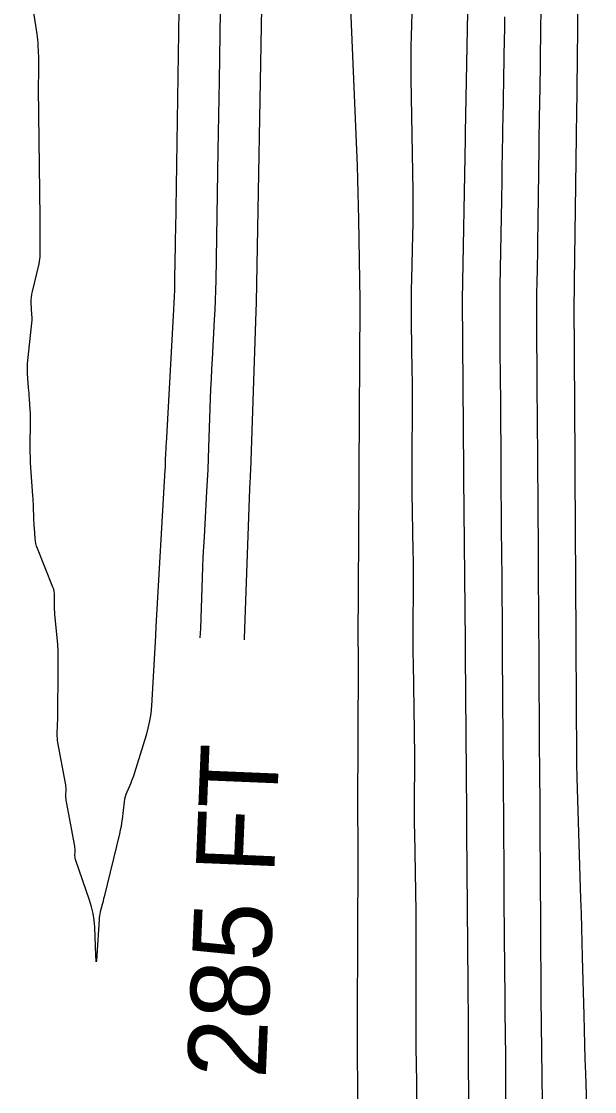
# Model space of a CAD drawing. Extents: x 1768942 to 1774819, y 723037 to 732099.
# Drawn here: x 1770471.7 to 1770515.4, y 730556.6 to 730638.3 of the extents above; entities that cross this region are included whole.
import ezdxf

# ---------------------------------------------------------------- set-up
doc = ezdxf.new("R2010")
doc.units = 0
doc.layers.add('R_Contour Annot', color=7, linetype='Continuous')
doc.layers.add('R_Contours', color=7, linetype='Continuous')

msp = doc.modelspace()

# ---------------------------------------------------------------- linework, layer by layer
at = {"layer": 'R_Contours'}
for points in [[(1770501.917, 730552.791), (1770501.837, 730559.061), (1770501.831, 730559.609), (1770501.826, 730560.157), (1770501.822, 730560.705), (1770501.821, 730561.253), (1770501.817, 730563.445), (1770501.816, 730563.993), (1770501.816, 730564.541), (1770501.817, 730565.089), (1770501.819, 730565.637), (1770501.829, 730568.039), (1770501.829, 730568.622), (1770501.827, 730569.205), (1770501.822, 730569.788), (1770501.813, 730570.371), (1770501.711, 730576.362), (1770501.702, 730577.008), (1770501.696, 730577.654), (1770501.694, 730578.3), (1770501.695, 730578.946), (1770501.708, 730581.529), (1770501.709, 730582.175), (1770501.707, 730582.821), (1770501.702, 730583.467), (1770501.693, 730584.113), (1770501.608, 730589.342), (1770501.598, 730590.051), (1770501.593, 730590.76), (1770501.591, 730591.469), (1770501.593, 730592.178), (1770501.609, 730595.014), (1770501.611, 730595.723), (1770501.61, 730596.432), (1770501.604, 730597.141), (1770501.595, 730597.85), (1770501.526, 730602.313), (1770501.517, 730603.086), (1770501.511, 730603.858), (1770501.51, 730604.631), (1770501.513, 730605.403), (1770501.533, 730608.493), (1770501.536, 730609.265), (1770501.535, 730610.038), (1770501.53, 730610.81), (1770501.52, 730611.583), (1770501.466, 730615.278), (1770501.458, 730616.114), (1770501.458, 730616.949), (1770501.467, 730617.784), (1770501.485, 730618.62), (1770501.571, 730621.96), (1770501.588, 730622.796), (1770501.596, 730623.631), (1770501.596, 730624.466), (1770501.587, 730625.302), (1770501.448, 730633.907), (1770501.439, 730634.721), (1770501.44, 730635.536), (1770501.45, 730636.35), (1770501.469, 730637.164), (1770501.767, 730647.369)], [(1770483.735, 730640.793), (1770483.437, 730622.303), (1770483.428, 730621.801), (1770483.42, 730621.299), (1770483.412, 730620.797), (1770483.403, 730620.295), (1770483.368, 730618.288), (1770483.357, 730617.786), (1770483.341, 730617.284), (1770483.32, 730616.783), (1770483.294, 730616.281), (1770482.721, 730606.065), (1770482.712, 730605.898), (1770482.704, 730605.73), (1770482.697, 730605.563), (1770482.691, 730605.396), (1770482.668, 730604.726), (1770482.662, 730604.559), (1770482.655, 730604.392), (1770482.646, 730604.225), (1770482.637, 730604.058), (1770481.948, 730592.095), (1770481.945, 730592.036), (1770481.942, 730591.978), (1770481.939, 730591.919), (1770481.937, 730591.86), (1770481.929, 730591.626), (1770481.927, 730591.567), (1770481.924, 730591.509), (1770481.921, 730591.45), (1770481.918, 730591.391), (1770481.601, 730586.045), (1770481.55, 730585.475), (1770481.465, 730584.91), (1770481.346, 730584.352), (1770481.194, 730583.8), (1770480.287, 730580.868), (1770480.229, 730580.688), (1770480.166, 730580.51), (1770480.098, 730580.333), (1770480.026, 730580.158), (1770479.728, 730579.462), (1770479.659, 730579.286), (1770479.604, 730579.107), (1770479.562, 730578.924), (1770479.533, 730578.738), (1770479.371, 730577.404), (1770479.332, 730577.12), (1770479.285, 730576.837), (1770479.23, 730576.556), (1770479.166, 730576.276), (1770477.995, 730571.473), (1770477.959, 730571.329), (1770477.923, 730571.185), (1770477.886, 730571.042), (1770477.849, 730570.899), (1770477.698, 730570.326), (1770477.664, 730570.182), (1770477.638, 730570.037), (1770477.618, 730569.891), (1770477.606, 730569.744), (1770477.452, 730567.012), (1770477.425, 730566.634), (1770477.4, 730566.508), (1770477.378, 730566.634), (1770477.358, 730567.013), (1770477.277, 730569.17), (1770477.238, 730569.694), (1770477.161, 730570.211), (1770477.044, 730570.72), (1770476.888, 730571.222), (1770475.828, 730574.242), (1770475.802, 730574.33), (1770475.784, 730574.419), (1770475.773, 730574.509), (1770475.771, 730574.6), (1770475.779, 730574.969), (1770475.779, 730575.061), (1770475.773, 730575.152), (1770475.764, 730575.244), (1770475.749, 730575.335), (1770475.122, 730578.728), (1770475.104, 730578.844), (1770475.091, 730578.962), (1770475.084, 730579.079), (1770475.083, 730579.197), (1770475.091, 730579.671), (1770475.09, 730579.789), (1770475.083, 730579.907), (1770475.07, 730580.024), (1770475.051, 730580.14), (1770474.471, 730583.253), (1770474.445, 730583.417), (1770474.428, 730583.582), (1770474.42, 730583.748), (1770474.421, 730583.914), (1770474.442, 730584.581), (1770474.447, 730584.747), (1770474.451, 730584.914), (1770474.454, 730585.081), (1770474.456, 730585.247), (1770474.495, 730588.843), (1770474.497, 730588.999), (1770474.497, 730589.156), (1770474.497, 730589.313), (1770474.495, 730589.469), (1770474.488, 730590.096), (1770474.485, 730590.252), (1770474.478, 730590.409), (1770474.469, 730590.565), (1770474.456, 730590.721), (1770474.242, 730593.041), (1770474.228, 730593.215), (1770474.218, 730593.389), (1770474.213, 730593.563), (1770474.212, 730593.738), (1770474.216, 730594.436), (1770474.209, 730594.609), (1770474.185, 730594.779), (1770474.145, 730594.946), (1770474.088, 730595.109), (1770472.904, 730598.05), (1770472.838, 730598.234), (1770472.787, 730598.423), (1770472.75, 730598.614), (1770472.729, 730598.809), (1770472.675, 730599.596), (1770472.662, 730599.792), (1770472.651, 730599.989), (1770472.642, 730600.186), (1770472.635, 730600.383), (1770472.607, 730601.243), (1770472.599, 730601.451), (1770472.589, 730601.66), (1770472.577, 730601.869), (1770472.563, 730602.077), (1770472.406, 730604.227), (1770472.382, 730604.623), (1770472.365, 730605.019), (1770472.357, 730605.415), (1770472.357, 730605.812), (1770472.376, 730607.768), (1770472.376, 730607.981), (1770472.372, 730608.193), (1770472.363, 730608.406), (1770472.35, 730608.618), (1770472.291, 730609.467), (1770472.276, 730609.679), (1770472.261, 730609.892), (1770472.246, 730610.104), (1770472.232, 730610.316), (1770472.156, 730611.398), (1770472.145, 730611.648), (1770472.144, 730611.899), (1770472.154, 730612.149), (1770472.176, 730612.4), (1770472.464, 730615.022), (1770472.484, 730615.243), (1770472.494, 730615.464), (1770472.495, 730615.685), (1770472.487, 730615.907), (1770472.437, 730616.794), (1770472.432, 730617.015), (1770472.444, 730617.234), (1770472.472, 730617.452), (1770472.516, 730617.669), (1770473.029, 730619.777), (1770473.067, 730619.955), (1770473.095, 730620.134), (1770473.111, 730620.314), (1770473.118, 730620.496), (1770473.122, 730621.245), (1770473.123, 730621.417), (1770473.123, 730621.589), (1770473.121, 730621.762), (1770473.119, 730621.934), (1770473.11, 730622.623), (1770473.107, 730622.795), (1770473.105, 730622.967), (1770473.103, 730623.14), (1770473.101, 730623.312), (1770472.997, 730633.147), (1770472.996, 730633.345), (1770472.996, 730633.543), (1770472.997, 730633.741), (1770473, 730633.938), (1770473.014, 730634.729), (1770473.016, 730634.927), (1770473.015, 730635.125), (1770473.012, 730635.322), (1770473.005, 730635.52), (1770472.969, 730636.432), (1770472.957, 730636.65), (1770472.939, 730636.867), (1770472.915, 730637.083), (1770472.884, 730637.299), (1770471.679, 730645.03)], [(1770514.198, 730642.238), (1770514.055, 730630.913), (1770514.053, 730630.796), (1770514.051, 730630.68), (1770514.05, 730630.563), (1770514.047, 730630.447), (1770514.039, 730629.98), (1770514.036, 730629.864), (1770514.034, 730629.747), (1770514.033, 730629.631), (1770514.031, 730629.514), (1770513.89, 730618.391), (1770513.888, 730618.258), (1770513.886, 730618.124), (1770513.884, 730617.991), (1770513.882, 730617.857), (1770513.871, 730617.324), (1770513.869, 730617.19), (1770513.868, 730617.057), (1770513.867, 730616.923), (1770513.868, 730616.79), (1770513.934, 730604.906), (1770513.935, 730604.813), (1770513.935, 730604.721), (1770513.936, 730604.628), (1770513.937, 730604.535), (1770513.94, 730604.164), (1770513.941, 730604.071), (1770513.941, 730603.978), (1770513.942, 730603.885), (1770513.942, 730603.792), (1770514.011, 730591.301), (1770514.011, 730591.261), (1770514.011, 730591.222), (1770514.012, 730591.182), (1770514.012, 730591.142), (1770514.013, 730590.983), (1770514.014, 730590.943), (1770514.014, 730590.903), (1770514.014, 730590.864), (1770514.014, 730590.824), (1770514.062, 730581.98), (1770514.065, 730581.623), (1770514.07, 730581.266), (1770514.078, 730580.909), (1770514.088, 730580.551), (1770514.376, 730571.325), (1770514.41, 730570.214), (1770514.442, 730569.104), (1770514.473, 730567.994), (1770514.502, 730566.884), (1770514.615, 730562.442), (1770514.645, 730561.332), (1770514.676, 730560.221), (1770514.71, 730559.111), (1770514.745, 730558.001), (1770515.444, 730536.883)], [(1770505.845, 730552.106), (1770505.806, 730562.913), (1770505.805, 730563.072), (1770505.804, 730563.231), (1770505.803, 730563.39), (1770505.802, 730563.548), (1770505.795, 730564.183), (1770505.793, 730564.342), (1770505.792, 730564.501), (1770505.79, 730564.66), (1770505.789, 730564.818), (1770505.692, 730576.426), (1770505.691, 730576.547), (1770505.69, 730576.667), (1770505.69, 730576.788), (1770505.689, 730576.908), (1770505.686, 730577.391), (1770505.686, 730577.512), (1770505.685, 730577.632), (1770505.684, 730577.753), (1770505.683, 730577.874), (1770505.581, 730589.955), (1770505.581, 730590.036), (1770505.58, 730590.117), (1770505.58, 730590.198), (1770505.579, 730590.28), (1770505.577, 730590.604), (1770505.577, 730590.686), (1770505.576, 730590.767), (1770505.576, 730590.848), (1770505.575, 730590.929), (1770505.469, 730603.479), (1770505.468, 730603.522), (1770505.468, 730603.564), (1770505.468, 730603.607), (1770505.467, 730603.649), (1770505.466, 730603.82), (1770505.466, 730603.862), (1770505.466, 730603.905), (1770505.466, 730603.947), (1770505.465, 730603.99), (1770505.354, 730617), (1770505.354, 730617.041), (1770505.354, 730617.055), (1770505.589, 730629.312), (1770505.59, 730629.352), (1770505.591, 730629.393), (1770505.591, 730629.433), (1770505.592, 730629.474), (1770505.594, 730629.635), (1770505.594, 730629.675), (1770505.595, 730629.716), (1770505.596, 730629.756), (1770505.596, 730629.797), (1770505.822, 730641.632)], [(1770511.457, 730555.794), (1770511.374, 730563.757), (1770511.37, 730564.218), (1770511.365, 730564.679), (1770511.361, 730565.139), (1770511.357, 730565.6), (1770511.342, 730567.443), (1770511.338, 730567.903), (1770511.335, 730568.364), (1770511.332, 730568.824), (1770511.329, 730569.285), (1770511.29, 730576.745), (1770511.287, 730577.256), (1770511.283, 730577.766), (1770511.28, 730578.277), (1770511.276, 730578.788), (1770511.258, 730580.83), (1770511.254, 730581.341), (1770511.251, 730581.852), (1770511.247, 730582.362), (1770511.244, 730582.873), (1770511.207, 730589.738), (1770511.204, 730590.298), (1770511.201, 730590.858), (1770511.196, 730591.418), (1770511.192, 730591.977), (1770511.173, 730594.216), (1770511.168, 730594.776), (1770511.164, 730595.336), (1770511.161, 730595.896), (1770511.157, 730596.455), (1770511.123, 730602.738), (1770511.119, 730603.346), (1770511.115, 730603.954), (1770511.111, 730604.561), (1770511.106, 730605.169), (1770511.085, 730607.601), (1770511.08, 730608.209), (1770511.076, 730608.817), (1770511.071, 730609.425), (1770511.068, 730610.032), (1770511.035, 730615.846), (1770511.034, 730616.449), (1770511.036, 730617.053), (1770511.042, 730617.656), (1770511.052, 730618.26), (1770511.098, 730620.674), (1770511.109, 730621.277), (1770511.119, 730621.881), (1770511.129, 730622.484), (1770511.137, 730623.088), (1770511.206, 730628.576), (1770511.214, 730629.156), (1770511.223, 730629.737), (1770511.233, 730630.317), (1770511.243, 730630.898), (1770511.287, 730633.22), (1770511.298, 730633.8), (1770511.308, 730634.381), (1770511.316, 730634.961), (1770511.324, 730635.542), (1770511.397, 730641.305)], [(1770488.719, 730591.084), (1770488.724, 730591.201), (1770489.119, 730602.571), (1770489.123, 730602.691), (1770489.128, 730602.811), (1770489.134, 730602.931), (1770489.141, 730603.051), (1770489.168, 730603.531), (1770489.175, 730603.651), (1770489.181, 730603.771), (1770489.186, 730603.891), (1770489.19, 730604.011), (1770489.601, 730616.135), (1770489.603, 730616.194), (1770489.606, 730616.252), (1770489.609, 730616.31), (1770489.612, 730616.368), (1770489.625, 730616.601), (1770489.628, 730616.659), (1770489.63, 730616.718), (1770489.632, 730616.776), (1770489.633, 730616.834), (1770490.05, 730640.716)], [(1770496.753, 730640.476), (1770497.305, 730627.247), (1770497.344, 730626.221), (1770497.377, 730625.194), (1770497.404, 730624.167), (1770497.423, 730623.14), (1770497.522, 730617.007), (1770497.523, 730616.992), (1770497.523, 730616.976), (1770497.522, 730616.961), (1770497.522, 730616.945), (1770497.521, 730616.883), (1770497.52, 730616.867), (1770497.52, 730616.852), (1770497.52, 730616.836), (1770497.52, 730616.82), (1770497.521, 730616.755), (1770497.521, 730616.739), (1770497.521, 730616.723), (1770497.521, 730616.707), (1770497.521, 730616.69), (1770497.438, 730603.975), (1770497.438, 730603.892), (1770497.438, 730603.809), (1770497.438, 730603.727), (1770497.439, 730603.644), (1770497.445, 730603.313), (1770497.446, 730603.231), (1770497.446, 730603.148), (1770497.446, 730603.065), (1770497.446, 730602.983), (1770497.378, 730591.057), (1770497.378, 730590.908), (1770497.378, 730590.759), (1770497.379, 730590.611), (1770497.381, 730590.462), (1770497.391, 730589.866), (1770497.393, 730589.717), (1770497.394, 730589.568), (1770497.395, 730589.42), (1770497.394, 730589.271), (1770497.341, 730578.131), (1770497.34, 730577.917), (1770497.341, 730577.702), (1770497.343, 730577.487), (1770497.346, 730577.272), (1770497.36, 730576.413), (1770497.364, 730576.199), (1770497.365, 730575.984), (1770497.366, 730575.769), (1770497.366, 730575.554), (1770497.333, 730567.303), (1770497.329, 730565.97), (1770497.326, 730564.637), (1770497.326, 730563.304), (1770497.327, 730561.971), (1770497.341, 730554.495)], [(1770486.865, 730639.05), (1770486.78, 730633.737), (1770486.758, 730632.408), (1770486.736, 730631.08), (1770486.713, 730629.751), (1770486.69, 730628.423), (1770486.517, 730618.505), (1770486.5, 730617.753), (1770486.476, 730617.001), (1770486.445, 730616.25), (1770486.407, 730615.498), (1770486.238, 730612.493), (1770486.198, 730611.742), (1770486.162, 730610.991), (1770486.13, 730610.239), (1770486.103, 730609.487), (1770485.976, 730605.755), (1770485.945, 730604.918), (1770485.909, 730604.082), (1770485.869, 730603.245), (1770485.823, 730602.41), (1770485.624, 730598.949), (1770485.581, 730598.172), (1770485.543, 730597.394), (1770485.509, 730596.616), (1770485.48, 730595.838), (1770485.372, 730592.725), (1770485.342, 730591.947), (1770485.311, 730591.226)], [(1770508.573, 730638.622), (1770508.565, 730638.082), (1770508.556, 730637.541), (1770508.547, 730637.001), (1770508.427, 730630.749), (1770508.418, 730630.237), (1770508.41, 730629.726), (1770508.402, 730629.215), (1770508.395, 730628.704), (1770508.369, 730626.659), (1770508.362, 730626.148), (1770508.354, 730625.637), (1770508.346, 730625.126), (1770508.336, 730624.614), (1770508.211, 730618.083), (1770508.203, 730617.566), (1770508.198, 730617.049), (1770508.196, 730616.532), (1770508.197, 730616.015), (1770508.208, 730613.947), (1770508.212, 730613.43), (1770508.215, 730612.913), (1770508.219, 730612.396), (1770508.223, 730611.879), (1770508.282, 730605.049), (1770508.286, 730604.489), (1770508.29, 730603.929), (1770508.294, 730603.369), (1770508.297, 730602.809), (1770508.31, 730600.57), (1770508.313, 730600.01), (1770508.316, 730599.45), (1770508.321, 730598.89), (1770508.325, 730598.33), (1770508.379, 730592.019), (1770508.384, 730591.416), (1770508.388, 730590.812), (1770508.392, 730590.209), (1770508.395, 730589.605), (1770508.408, 730587.191), (1770508.412, 730586.588), (1770508.416, 730585.984), (1770508.42, 730585.381), (1770508.425, 730584.777), (1770508.474, 730578.995), (1770508.479, 730578.347), (1770508.484, 730577.699), (1770508.488, 730577.051), (1770508.491, 730576.403), (1770508.505, 730573.811), (1770508.509, 730573.163), (1770508.513, 730572.516), (1770508.518, 730571.868), (1770508.523, 730571.22), (1770508.567, 730565.959), (1770508.573, 730565.274), (1770508.579, 730564.59), (1770508.585, 730563.905), (1770508.592, 730563.221), (1770508.621, 730560.483), (1770508.628, 730559.799), (1770508.633, 730559.114), (1770508.637, 730558.43), (1770508.64, 730557.745), (1770508.657, 730553.218)]]:
    msp.add_lwpolyline(points, dxfattribs=at)

# ---------------------------------------------------------------- texts
at = {"layer": 'R_Contour Annot'}
msp.add_text('285 FT', height=6, rotation=87.62137, dxfattribs=at).set_placement((1770490.329, 730557.563))

doc.saveas('drawing.dxf')
